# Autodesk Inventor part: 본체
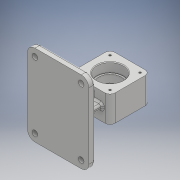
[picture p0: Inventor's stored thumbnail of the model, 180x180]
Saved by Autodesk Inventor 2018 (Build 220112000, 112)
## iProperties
Created: 2020-11
Part Number: 본체
Material: Generic
Document SubType Name: Modeling
Designer: Administrator
Density: 1 g/cm^3
Appearance: Default
Author: Administrator
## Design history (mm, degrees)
sketch "스케치1"
  geometry: L1 (-32, -32)-(32, -32); L2 (32, -32)-(32, 32); L3 (32, 32)-(-32, 32); L4 (-32, 32)-(-32, -32); L5 (-32, -32)-(32, 32); L6 (32, -32)-(-32, 32); 1 further point
  constraints: 12 end point, 2 midpoint, 2 parallel, 1 horizontal, 1 perpendicular
  dimensions: "d1" = 64 distance of L3.end L2.end; "d2" = 64 distance of L2.end L1.end
extrude "돌출1" new body sketch "스케치1" stored distance "d3" = 42; taper "d4" = 0 deg
sketch "스케치2"
  geometry: L1 (32, 21)-(-32, 21) reference; L2 (0, 21)-(21, 21); L3 (21, 21)-(21, 6); L4 (21, 6)-(0, 6); L5 (0, 6)-(0, 21); L6 (-32, -21)-(32, -21) reference; L7 (0, -21)-(21, -21); L8 (21, -21)-(21, -6); L9 (21, -6)-(0, -6); L10 (0, -6)-(0, -21); L11 (0, 6)-(18, 6); L12 (18, 6)-(18, -6); L13 (18, -6)-(0, -6); L14 (0, -6)-(0, 6); 1 further point
  constraints: 24 end point, 6 parallel, 3 horizontal, 3 perpendicular, 2 midpoint, 1 point on line
  dimensions: "d5" = 21 distance of L3.end L4.end; "d6" = 15 distance of L2.end L3.end; "d7" = 21 distance of L9.end L8.end; "d8" = 15 distance of L8.end L7.end; "d9" = 18 distance of L12.end L13.end
revolve "회전1" sketch "스케치2" stored, may be unused: angle "d10" = 90 deg
sketch "스케치3"
  geometry: L1 (-24, -24)-(24, -24); L2 (24, -24)-(24, 24); L3 (24, 24)-(-24, 24); L4 (-24, 24)-(-24, -24); L5 (-24, -24)-(24, 24); L6 (24, -24)-(-24, 24); 5 further points
  constraints: 12 end point, 4 coincident, 2 midpoint, 2 parallel, 1 horizontal, 1 perpendicular
  dimensions: "d11" = 48 distance of L3.end L2.end; "d12" = 48 distance of L2.end L1.end
hole "구멍1" sketch "스케치3" at (-24, 24), (24, 24), (24, -24), (-24, -24) diameter "d13" = 3.242; stored, may be unused: countersink angle "d17" = 90 deg, drill point angle "d19" = 118 deg; dims "d14" = 8, "d15" = 4, "d16" = 2, "d18" = 10
fillet "모깎기1" dims "d20" = 8
node "작업 평면1"
sketch "스케치4"
  geometry: L1 (0, 0)-(62, 0); L2 (62, 0)-(62, -65); L3 (62, -65)-(-36, -65); L4 (-36, -65)-(-36, 65); L5 (-36, 65)-(62, 65); L6 (62, 65)-(62, 0)
  constraints: 12 end point, 2 perpendicular, 2 vertical, 1 horizontal
  dimensions: "d45" = 62 distance of L1.start L1.end; "d46" = 65 distance of L1.end L2.end; "d47" = 98 distance of L2.end L3.end; "d48" = 130 distance of L3.end L4.end; "d49" = 98 distance of L4.end L5.end
extrude "돌출2" join sketch "스케치4" distance "d50" = 10; taper "d51" = 0 deg
sketch "스케치5"
  geometry: L1 (-4, -17)-(4, -17); L2 (4, -17)-(4, 17); L3 (4, 17)-(-4, 17); L4 (-4, 17)-(-4, -17); L5 (-4, -17)-(4, 17); L6 (4, -17)-(-4, 17); 1 further point
  constraints: 12 end point, 2 midpoint, 2 parallel, 1 horizontal, 1 perpendicular
  dimensions: "d52" = 8 distance of L3.end L2.end; "d53" = 34 distance of L2.end L1.end
extrude "돌출3" join sketch "스케치5" stored distance "d54" = 10; taper "d55" = 0 deg
sketch "스케치6"
  geometry: L1 (-20, -4)-(20, -4); L2 (20, -4)-(20, 4); L3 (20, 4)-(-20, 4); L4 (-20, 4)-(-20, -4); L5 (-20, -4)-(20, 4); L6 (20, -4)-(-20, 4); 1 further point
  constraints: 12 end point, 2 midpoint, 2 parallel, 1 horizontal, 1 perpendicular
  dimensions: "d56" = 40 distance of L3.end L2.end; "d57" = 8 distance of L2.end L1.end
extrude "돌출4" join sketch "스케치6" stored distance "d58" = 10; taper "d59" = 0 deg
sketch "스케치7"
  geometry: C1 r 18 at (0, 0); 1 further point
  constraints: 1 centre point, 1 coincident
extrude "돌출5" cut sketch "스케치7" distance "d60" = 10; taper "d61" = 0 deg
fillet "모깎기2" dims "d62" = 12
sketch "스케치8"
  geometry: C1 r 4.5 at (24, -53); C2 r 4.5 at (-50, -53); C3 r 4.5 at (24, 53); C4 r 4.5 at (-50, 53); A1 r 12 centre (24, -53) between (24, -65) and (36, -53) reference; A2 r 12 centre (-50, -53) between (-62, -53) and (-50, -65) reference; A3 r 12 centre (24, 53) between (36, 53) and (24, 65) reference; 1 further point
  constraints: 4 centre point, 3 coincident
  dimensions: "d63" = 9 diameter of C1; "d64" = 9 diameter of C2; "d66" = 9 diameter of C3; "d67" = 9 diameter of C4; "d68" = 86 distance of A3.start C4.centre; "d69" = 136.49908 distance of A1.end C4.centre
extrude "돌출6" cut sketch "스케치8" distance "d70" = 10; taper "d71" = 0 deg
fillet "모깎기3" dims "d72" = 3
fillet "모깎기4" dims "d73" = 3
fillet "모깎기5" dims "d74" = 3
chamfer "모따기1" distance "d75" = 1; stored, may be unused: second distance "d76" = 2, angle "d77" = 45 deg
fillet "모깎기6" dims "d78" = 0.3
sketch "스케치9"
  geometry: L1 (-62, 53)-(-62, -53) reference; L2 (-62, 0)-(-52, 0); 2 further points
  constraints: 2 coincident, 2 end point, 1 horizontal, 1 midpoint, 1 other
  dimensions: "d79" = 10 distance of L2.start L2.end
feature "엠보싱1" sketch "스케치9" dims "d1" = 64, "d2" = 64, "d5" = 21, "d6" = 15, "d7" = 21, "d8" = 15, "d9" = 18, "d80" = 0.5, "d81" = 0
node "솔리드1"
mirror "미러1"
